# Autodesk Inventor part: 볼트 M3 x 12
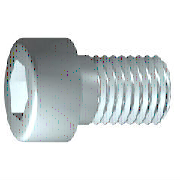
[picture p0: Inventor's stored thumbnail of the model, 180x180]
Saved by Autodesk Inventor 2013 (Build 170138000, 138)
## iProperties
IsCustomPart: 0
Created: 2012-02
Part Number: 볼트 M3 x 12
Material: 강철, 연강
Description: 6각머리 태핑 나사
Document SubType Name: Modeling
Standard: KS B 1003
Designer: mduedu
Standards Organization: KS
Language: ko-KR
Size Designation: M 3 x 12
Categories: <MemberInstance><Categories><Category DisplayName="조임쇠" InternalName="e4da775c-781d-43d5-af7c-5136215cf5a6" Mnemonic="FSTN"><Category DisplayName="볼트" InternalN
Density: 7.86 g/cm^3
Mass: 1.20764 g
Surface Area: 2.30125 cm^2
Volume: 0.153644 cm^3
Author: mduedu
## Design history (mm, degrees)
sketch "스케치1"
  geometry: L1 (-0.867, 0)-(13, 0); L2 (13, 0)-(13, 1.5); L3 (13, 1.5)-(1.25, 1.5); L4 (1.25, 1.5)-(0.943, 1.5); L5 (0.943, 1.5)-(0, 1.5); L6 (0, 1.5)-(0, 2.75); L7 (0, 2.75)-(-3, 2.75); L8 (-3, 2.75)-(-3, 1.443); L9 (-3, 1.443)-(-1.7, 1.443); L10 (-1.7, 1.443)-(-0.867, 0); L11 (-6.2, 0)-(16.2, 0) reference; L12 (0, -0.55)-(0, 3.3) reference; L13 (1.25, 1.5)-(0, 1.5)
  constraints: 22 end point, 6 parallel, 2 collinear, 2 perpendicular, 1 horizontal, 1 point on line
  dimensions: "d1" = 11.75 distance from line of L3.end L2 (= GEL); "d2" = 0.30683 distance of L4.end L3.end (computed from GAL); "d3" = 3 distance between parallel lines of L8 L6 (= KOH); "d4" = 1.3 distance of L8.end L9.end (= INTI); "d5" = 60 deg angle of L10 L1; "d6" = 3 diameter of L3 L1 (= GD); "d7" = 3 diameter of L5 L1 (= BDM); "d8" = 2.88675 diameter of L9 L1 (= 1.1547 x SW); "d9" = 5.5 diameter of L7 L1 (= KOD); "d26" = 13 distance between parallel lines of L12 L2 (= NLG)
revolve "본체" sketch "스케치1" stored, may be unused: angle "d10" = 90 deg
sketch "스케치2"
  geometry: L1 (0, -3.85)-(0, 3.85) reference; L2 (-3.85, 0)-(3.85, 0) reference; L3 (1.443, 0)-(0.722, -1.25); L4 (0.722, -1.25)-(-0.722, -1.25); L5 (-0.722, -1.25)-(-1.443, 0); L6 (-1.443, 0)-(-0.722, 1.25); L7 (-0.722, 1.25)-(0.722, 1.25); L8 (0.722, 1.25)-(1.443, 0); 2 further points
  constraints: 12 end point, 1 coincident, 1 horizontal alignment, 1 point on line, 12 other
extrude "슬롯" join sketch "스케치2" stored distance "d11" = 10; taper "d12" = 0 deg
workplane "Work Plane1"
fillet "Fillet2" dims "d30" = 0.1 (= R)
body "Solid1"
fillet "모깎기1" dims "d17" = 0.3 (= RR)
feature "스레드" dims "d13" = 11.75 (= GEL), "d14" = 0
chamfer "모따기1" distance "d15" = 0.30673 (= -0.5 x SPD + 0.5 x GD); stored, may be unused: second distance "d16" = 0.30673 (= GUL), angle "d27" = 45 deg
other parameters: "GD" = 3 (= NND) [user parameter; used in 2 equation terms], "NLG" = 13 [user parameter; used in 1 equation term], "GEL" = 11.75 [user parameter; used in 2 equation terms], "KOD" = 5.5 [user parameter; used in 1 equation term], "KOH" = 3 [user parameter; used in 1 equation term], "INTI" = 1.3 [user parameter; used in 1 equation term], "GAL" = 0.30673 (= 0.61345 x PTC) [user parameter; used in 1 equation term], "GUL" = 0.30673 (= 0.61345 x PTC) [user parameter; used in 1 equation term], "BDM" = 3 (= NND) [user parameter; used in 1 equation term], "SW" = 2.5 [user parameter; used in 2 equation terms], "RR" = 0.3 [user parameter; used in 1 equation term], "SPD" = 2.38655 (= NND - 1.2269 x PTC) [user parameter; used in 1 equation term], "d19" = 0, "d28" = 0, "d29" = 0, "R" = 0.1 [user parameter; used in 1 equation term], "PHH" = 0.1 [user parameter], "GD1" = 2.38655 (= THREADDIA - 1.2269 x PTC) [user parameter], "THREADDIA" = 3 [user parameter; used in 1 equation term], "FAWI" = 45 deg [user parameter], "PTC" = 0.5 [user parameter; used in 5 equation terms], "NND" = 3 [user parameter; used in 3 equation terms], "TOA" = 30 deg [user parameter], "E0" = 2.8875 (= 1.155 x SW) [user parameter]
